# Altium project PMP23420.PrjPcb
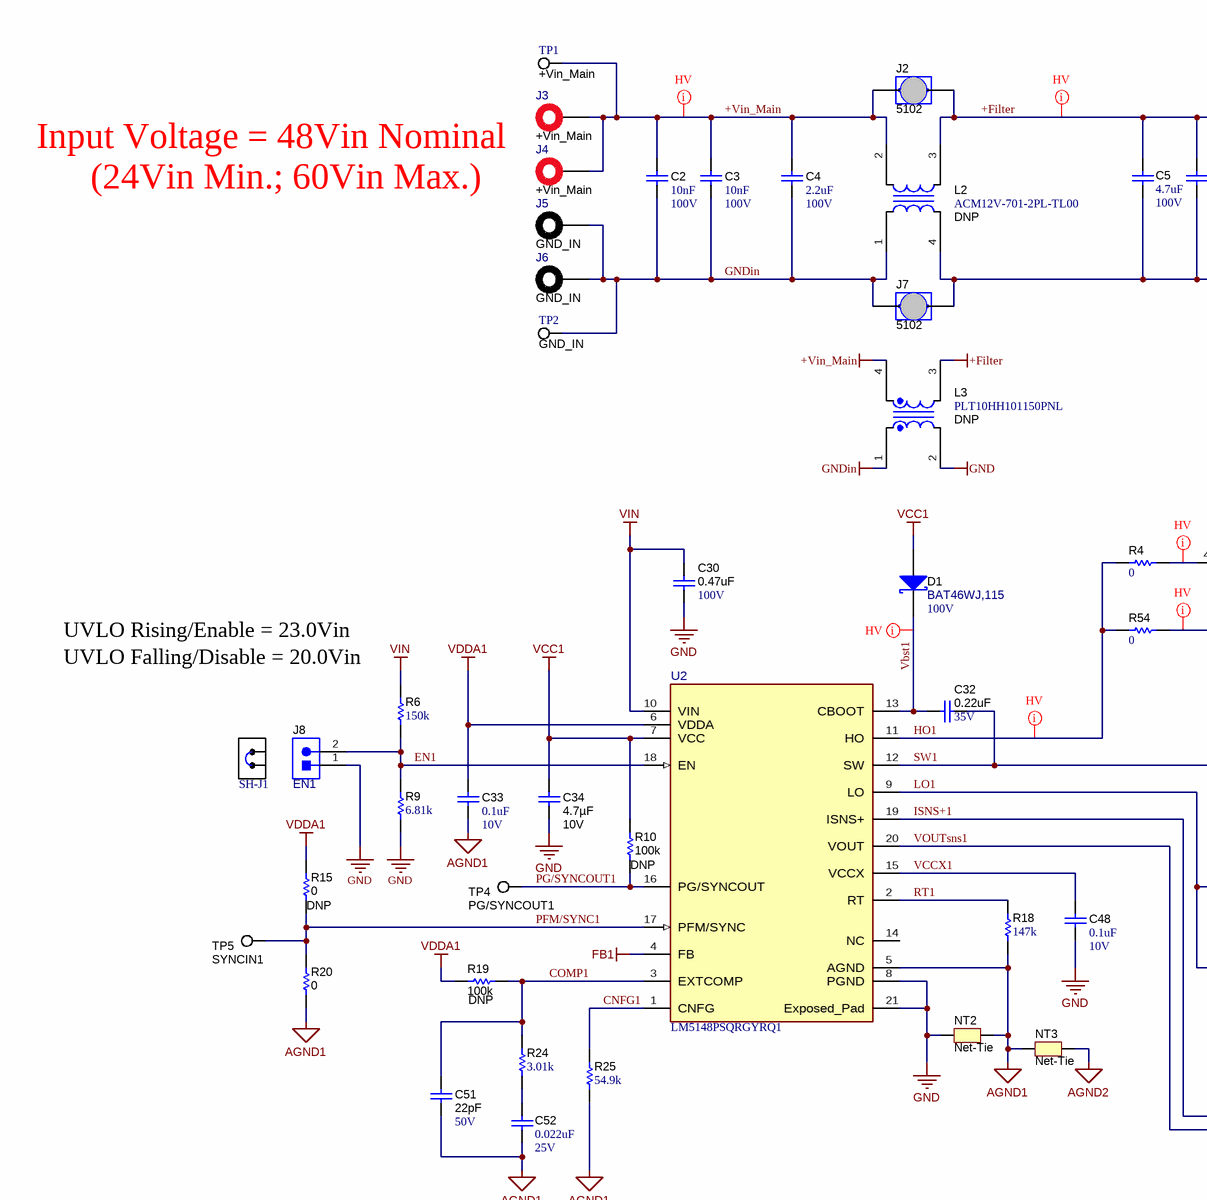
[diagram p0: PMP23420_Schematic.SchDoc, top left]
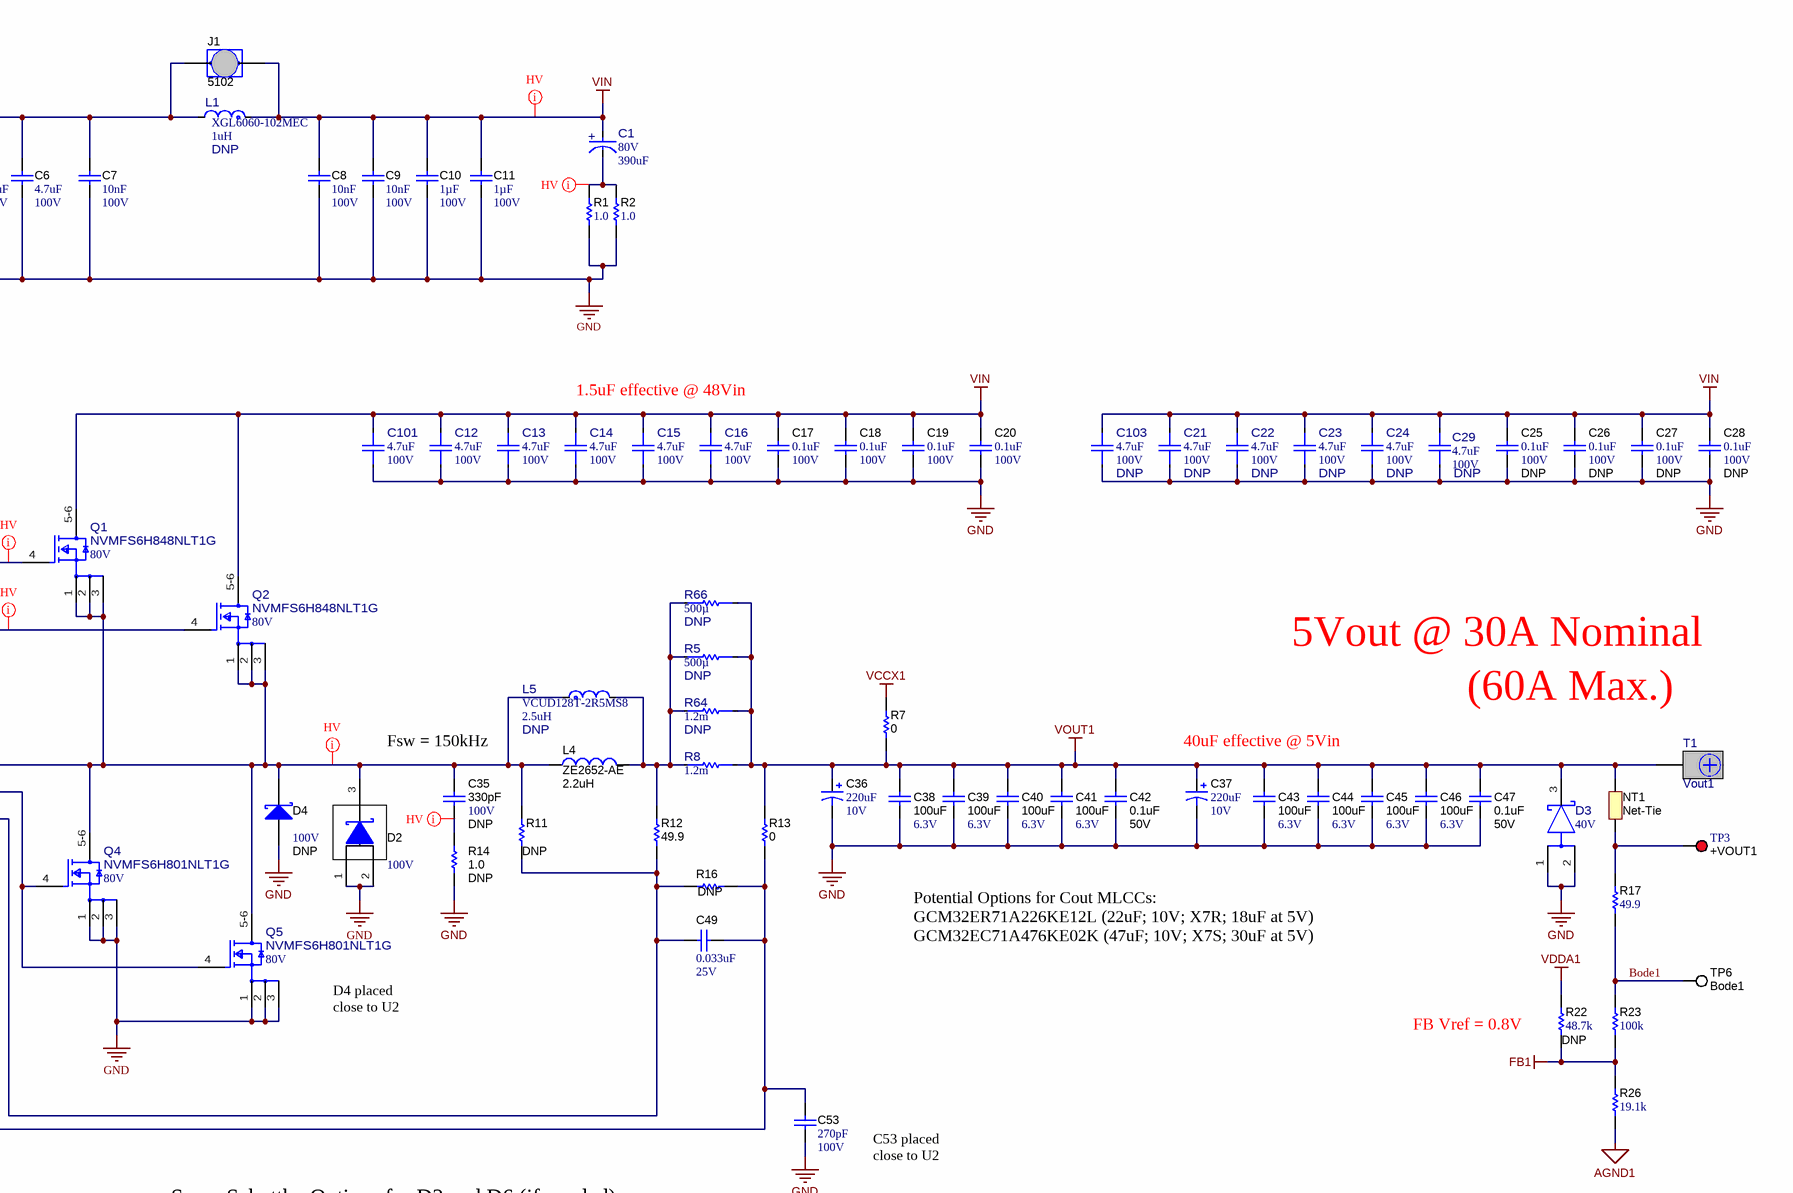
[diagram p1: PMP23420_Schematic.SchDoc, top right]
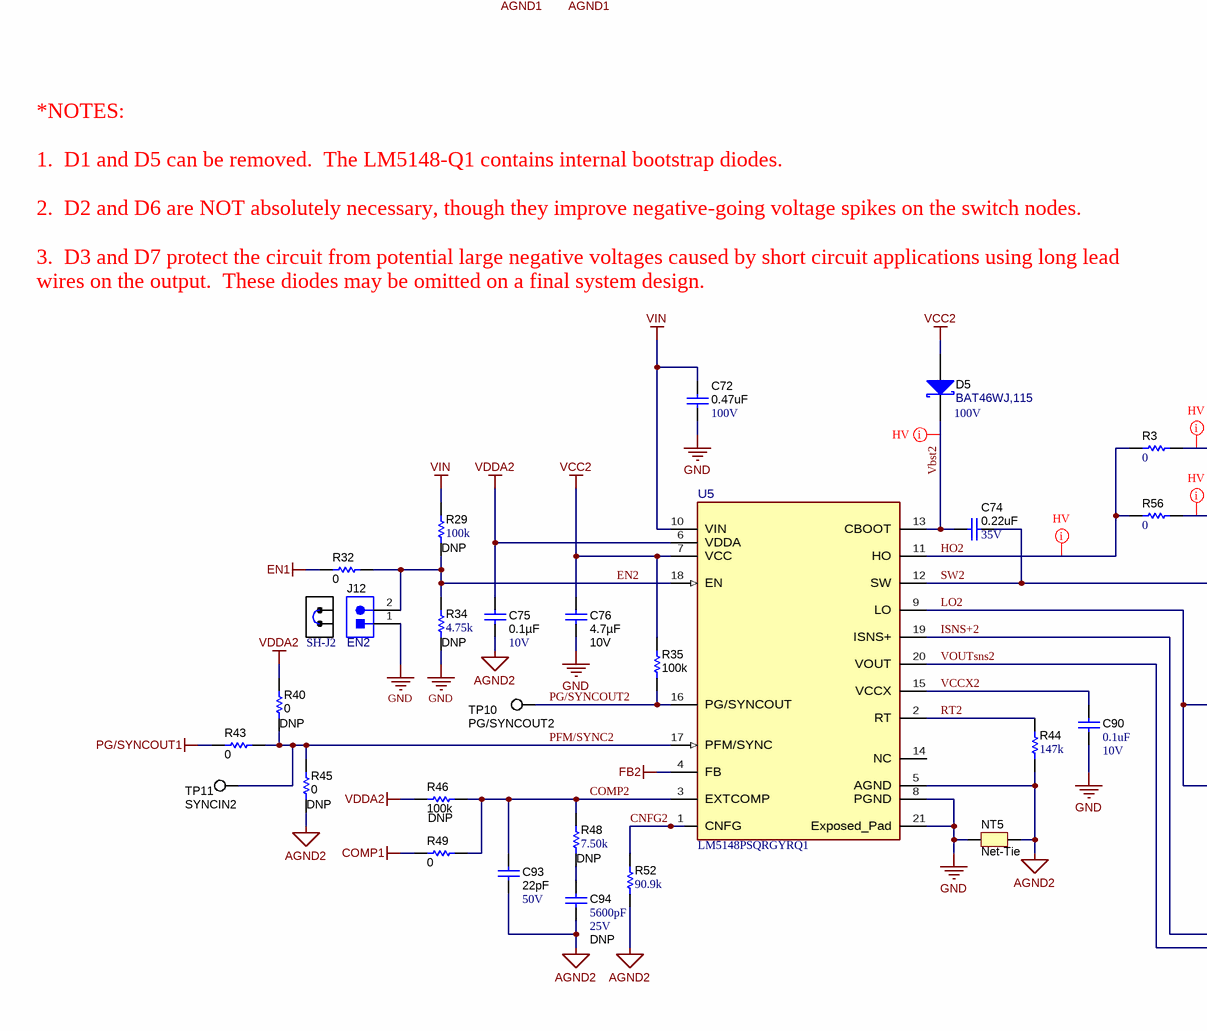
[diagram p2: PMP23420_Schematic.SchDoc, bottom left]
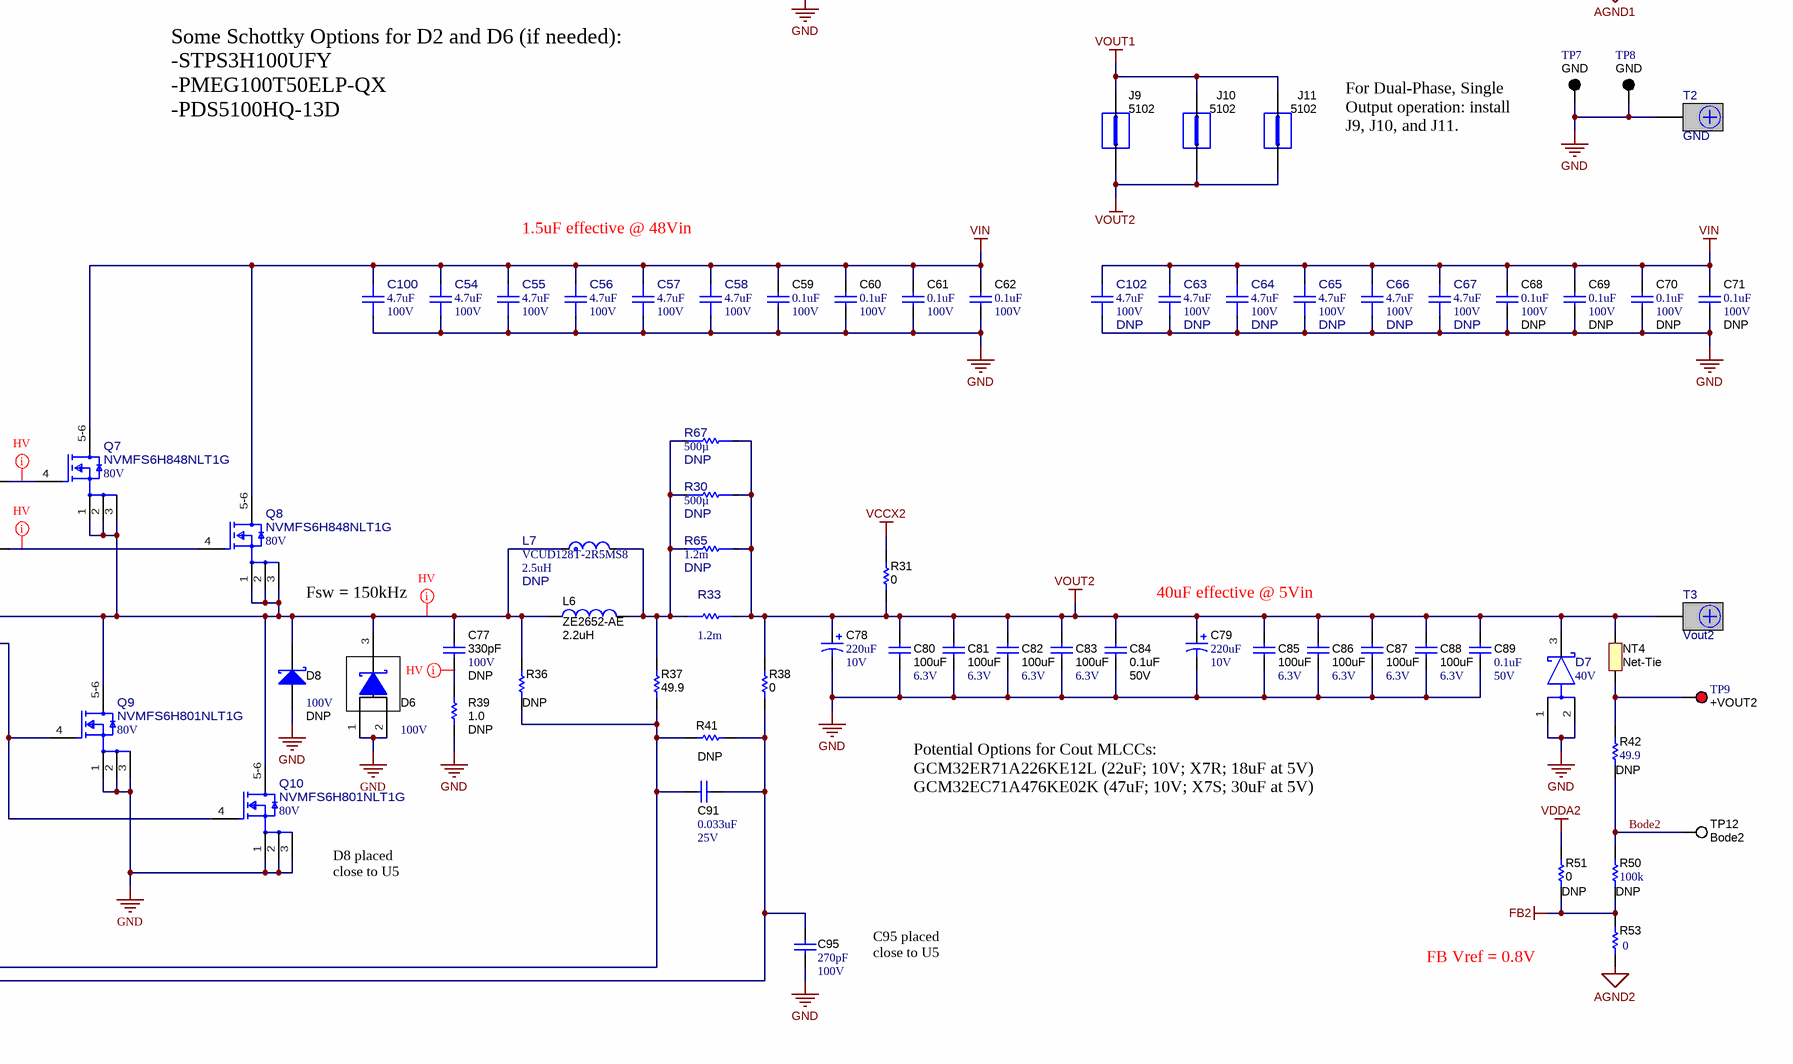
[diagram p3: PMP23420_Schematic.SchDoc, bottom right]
TID: PMP23420; TechSupport: http://www.ti.com/support; SCH_Rev: -1; PRJ_Title: LM5148-Q1 2-PH Buck Converter Using Si FETs; PRJ_Number: PMP23420; PRJ_Engineer: Hrag Kasparian; PCB_Rev: A; PCB_Layout: Hrag Kasparian; CopyrightYear: 2024
2 sheets, 228 parts. Net scope: global (net labels, ports and power ports of the same name join across sheets).
Board file: PMP23420.PcbDoc
Sheets:
  PMP23420_Schematic.SchDoc
  PMP23420_Hardware.SchDoc

## Sheet PMP23420_Schematic.SchDoc
size 558 x 431 mm; Date: Not shown in title block; ApprovedBy: Not shown in title block; CheckedBy: Not shown in title block; Author: Not shown in title block; CompanyName: Not shown in title block; Engineer: Not shown in title block; Organization: Not shown in title block; Address1: Not shown in title block; Address2: Not shown in title block; Address3: Not shown in title block; Address4: Not shown in title block; DocumentNumber: 1; Revision: Use project parameter SCH_Rev; SheetNumber: 1; SheetTotal: 2; PageSetup: Record=PageOptions¦CenterHorizontal=True¦CenterVertical=True¦PrintScale=1.00¦XCorrection=1.00¦YCorrection=1.00¦PrintKind=0¦BorderSize=5000000¦LeftOffset=0¦BottomOffset=0¦Orientation=2¦PaperLength=1000¦PaperWidth=1000¦Scale=100¦PaperSource=15¦PrintQuality=600¦MediaType=1¦DitherType=10¦PaperKind=Letter¦PrintScaleMode=1; SPICEModelCacheOPLTMGFQ: <root> / <DocumentId>OPLTMGFQ</DocumentId> / <CacheFrame Number="0"> / <Model Name="skydiode" Kind="MDL"> / <Text>*Default Schottky Diode / *Schottky Diode Pinout: A,K / .MODEL SKYDIODE D(EG=0.69 XTI=2)</Text> / </Model> / </CacheFrame> / </root>

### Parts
C1  VDC_V: 80V  ValueDisplayed: 390uF  [FP-EEE-TP1K391V_SMT_CAP_17MM0_17MM0-MFG]  (hidden comment: EEE-TP1K391V)
C2  Cap_F: 10nF  VDC_V: 100V  [0603_HV]  (hidden comment: GCM188R72A103KA37J)
C3  Cap_F: 10nF  VDC_V: 100V  [0603_HV]  (hidden comment: GCM188R72A103KA37J)
C4  VDC_V: 100V  ValueDisplayed: 2.2uF  [1206_180]  (hidden comment: CGA5L3X7S2A225K160AB)
C5  ValueDisplayed: 4.7uF  VDC_V: 100V  [1210_220]  (hidden comment: C3225X7S2A475K200AB)
C6  ValueDisplayed: 4.7uF  VDC_V: 100V  [1210_220]  (hidden comment: CGA6M3X7S2A475K200AB)
C7  Cap_F: 10nF  VDC_V: 100V  [0603L]  (hidden comment: GCM188R72A103KA37J)
C8  Cap_F: 10nF  VDC_V: 100V  [0603]  (hidden comment: GCM188R72A103KA37J)
C9  Cap_F: 10nF  VDC_V: 100V  [0603]  (hidden comment: GCM188R72A103KA37J)
C10  Cap_F: 1µF  VDC_V: 100V  [0805_150]  (hidden comment: 08051C105K4Z2A)
C11  Cap_F: 1µF  VDC_V: 100V  [0805_150]  (hidden comment: 08051C105K4Z2A)
C12  ValueDisplayed: 4.7uF  VDC_V: 100V  [FP-GCJ32DC72A475KE01L_1210-MFG]  (hidden comment: GCJ32DC72A475KE01L)
C13  ValueDisplayed: 4.7uF  VDC_V: 100V  [FP-GCJ32DC72A475KE01L_1210-MFG]  (hidden comment: GCJ32DC72A475KE01L)
C14  ValueDisplayed: 4.7uF  VDC_V: 100V  [FP-GCJ32DC72A475KE01L_1210-MFG]  (hidden comment: GCJ32DC72A475KE01L)
C15  ValueDisplayed: 4.7uF  VDC_V: 100V  [FP-GCJ32DC72A475KE01L_1210-MFG]  (hidden comment: GCJ32DC72A475KE01L)
C16  ValueDisplayed: 4.7uF  VDC_V: 100V  [FP-GCJ32DC72A475KE01L_1210-MFG]  (hidden comment: GCJ32DC72A475KE01L)
C17  VDC_V: 100V  ValueDisplayed: 0.1uF  [0603L]  (hidden comment: GCJ188R72A104KA01D)
C18  VDC_V: 100V  ValueDisplayed: 0.1uF  [0603L]  (hidden comment: GCJ188R72A104KA01D)
C19  VDC_V: 100V  ValueDisplayed: 0.1uF  [0603L]  (hidden comment: GCJ188R72A104KA01D)
C20  VDC_V: 100V  ValueDisplayed: 0.1uF  [0603L]  (hidden comment: GCJ188R72A104KA01D)
C21  DNP  ValueDisplayed: 4.7uF  VDC_V: 100V  [FP-GCJ32DC72A475KE01L_1210-MFG]
C22  DNP  ValueDisplayed: 4.7uF  VDC_V: 100V  [FP-GCJ32DC72A475KE01L_1210-MFG]
C23  DNP  ValueDisplayed: 4.7uF  VDC_V: 100V  [FP-GCJ32DC72A475KE01L_1210-MFG]
C24  DNP  ValueDisplayed: 4.7uF  VDC_V: 100V  [FP-GCJ32DC72A475KE01L_1210-MFG]
C25  DNP  VDC_V: 100V  ValueDisplayed: 0.1uF  [0603L]
C26  DNP  VDC_V: 100V  ValueDisplayed: 0.1uF  [0603L]
C27  DNP  VDC_V: 100V  ValueDisplayed: 0.1uF  [0603L]
C28  DNP  VDC_V: 100V  ValueDisplayed: 0.1uF  [0603L]
C29  DNP  ValueDisplayed: 4.7uF  VDC_V: 100V  [FP-GCJ32DC72A475KE01L_1210-MFG]
C30  value 0.47uF  Value1: 100V  [0805L]  (hidden comment: KAF21KR72A474KU)
C32  value 0.22uF  Value1: 35V  [0402L]  (hidden comment: CGA2B1X7R1V224K050BC)
C33  value 0.1uF  Value2: 10V  [0402L]  (hidden comment: C0402C104K8RACAUTO)
C34  Cap_F: 4.7µF  Value2: 10V  [0603L]  (hidden comment: GRM188Z71A475ME15D)
C35  DNP  value 330pF  Value1: 100V  [0603L]
C36  value 220uF  VDC_V: 10V  [7343-31]
C37  value 220uF  VDC_V: 10V  [7343-31]
C38  value 100uF  Value1: 6.3V  [1210L]  (hidden comment: GRT32EC70J107ME13K)
C39  value 100uF  Value1: 6.3V  [1210L]  (hidden comment: GRT32EC70J107ME13K)
C40  value 100uF  Value1: 6.3V  [1210L]  (hidden comment: GRT32EC70J107ME13K)
C41  value 100uF  Value1: 6.3V  [1210L]  (hidden comment: GRT32EC70J107ME13K)
C42  Value2: 50V  Cap_F: 0.1uF  [0603L]  (hidden comment: C0603C104K5RACTU)
C43  value 100uF  Value1: 6.3V  [1210L]  (hidden comment: GRT32EC70J107ME13K)
C44  value 100uF  Value1: 6.3V  [1210L]  (hidden comment: GRT32EC70J107ME13K)
C45  value 100uF  Value1: 6.3V  [1210L]  (hidden comment: GRT32EC70J107ME13K)
C46  value 100uF  Value1: 6.3V  [1210L]  (hidden comment: GRT32EC70J107ME13K)
C47  ValueDisplayed: 0.1uF  Value2: 50V  [0603L]  (hidden comment: Capacitor)
C48  value 0.1uF  Value2: 10V  [0402L]  (hidden comment: C0402C104K8RACAUTO)
C49  ValueDisplayed: 0.033uF  Value2: 25V  [0402L]  (hidden comment: CGA2B1X7R1E333K050BC)
C51  ValueDisplayed: 22pF  Value2: 50V  [0402L]  (hidden comment: CGA2B2NP01H220J050BA)
C52  ValueDisplayed: 0.022uF  VDC_V: 25V  [0402L]  (hidden comment: GCM155R71E223KA55D)
C53  ValueDisplayed: 270pF  VDC_V: 100V  [0402L]  (hidden comment: GRM155R72A271KA01D)
C54  ValueDisplayed: 4.7uF  VDC_V: 100V  [FP-GCJ32DC72A475KE01L_1210-MFG]  (hidden comment: GCJ32DC72A475KE01L)
C55  ValueDisplayed: 4.7uF  VDC_V: 100V  [FP-GCJ32DC72A475KE01L_1210-MFG]  (hidden comment: GCJ32DC72A475KE01L)
C56  ValueDisplayed: 4.7uF  VDC_V: 100V  [FP-GCJ32DC72A475KE01L_1210-MFG]  (hidden comment: GCJ32DC72A475KE01L)
C57  ValueDisplayed: 4.7uF  VDC_V: 100V  [FP-GCJ32DC72A475KE01L_1210-MFG]  (hidden comment: GCJ32DC72A475KE01L)
C58  ValueDisplayed: 4.7uF  VDC_V: 100V  [FP-GCJ32DC72A475KE01L_1210-MFG]  (hidden comment: GCJ32DC72A475KE01L)
C59  VDC_V: 100V  ValueDisplayed: 0.1uF  [0603L]  (hidden comment: GCJ188R72A104KA01D)
C60  VDC_V: 100V  ValueDisplayed: 0.1uF  [0603L]  (hidden comment: GCJ188R72A104KA01D)
C61  VDC_V: 100V  ValueDisplayed: 0.1uF  [0603L]  (hidden comment: GCJ188R72A104KA01D)
C62  VDC_V: 100V  ValueDisplayed: 0.1uF  [0603L]  (hidden comment: GCJ188R72A104KA01D)
C63  DNP  ValueDisplayed: 4.7uF  VDC_V: 100V  [FP-GCJ32DC72A475KE01L_1210-MFG]
C64  DNP  ValueDisplayed: 4.7uF  VDC_V: 100V  [FP-GCJ32DC72A475KE01L_1210-MFG]
C65  DNP  ValueDisplayed: 4.7uF  VDC_V: 100V  [FP-GCJ32DC72A475KE01L_1210-MFG]
C66  DNP  ValueDisplayed: 4.7uF  VDC_V: 100V  [FP-GCJ32DC72A475KE01L_1210-MFG]
C67  DNP  ValueDisplayed: 4.7uF  VDC_V: 100V  [FP-GCJ32DC72A475KE01L_1210-MFG]
C68  DNP  VDC_V: 100V  ValueDisplayed: 0.1uF  [0603L]
C69  DNP  VDC_V: 100V  ValueDisplayed: 0.1uF  [0603L]
C70  DNP  VDC_V: 100V  ValueDisplayed: 0.1uF  [0603L]
C71  DNP  VDC_V: 100V  ValueDisplayed: 0.1uF  [0603L]
C72  value 0.47uF  Value1: 100V  [0805L]  (hidden comment: KAF21KR72A474KU)
C74  value 0.22uF  Value1: 35V  [0402L]  (hidden comment: CGA2B1X7R1V224K050BC)
C75  ValueDisplayed: 0.1µF  Value2: 10V  [0402L]  (hidden comment: C0402C104K8RACAUTO)
C76  Cap_F: 4.7µF  Value2: 10V  [0603L]  (hidden comment: GRM188Z71A475ME15D)
C77  DNP  value 330pF  Value1: 100V  [0603L]
C78  value 220uF  VDC_V: 10V  [7343-31]
C79  value 220uF  VDC_V: 10V  [7343-31]
C80  value 100uF  Value1: 6.3V  [1210L]  (hidden comment: GRT32EC70J107ME13K)
C81  value 100uF  Value1: 6.3V  [1210L]  (hidden comment: GRT32EC70J107ME13K)
C82  value 100uF  Value1: 6.3V  [1210L]  (hidden comment: GRT32EC70J107ME13K)
C83  value 100uF  Value1: 6.3V  [1210L]  (hidden comment: GRT32EC70J107ME13K)
C84  value 0.1uF  Value2: 50V  [0603L]  (hidden comment: C0603C104K5RACTU)
C85  value 100uF  Value1: 6.3V  [1210L]  (hidden comment: GRT32EC70J107ME13K)
C86  value 100uF  Value1: 6.3V  [1210L]  (hidden comment: GRT32EC70J107ME13K)
C87  value 100uF  Value1: 6.3V  [1210L]  (hidden comment: GRT32EC70J107ME13K)
C88  value 100uF  Value1: 6.3V  [1210L]  (hidden comment: GRT32EC70J107ME13K)
C89  value 0.1uF  VDC_V: 50V  [0603L]  (hidden comment: C0603C104K5RACTU)
C90  value 0.1uF  Value2: 10V  [0402L]  (hidden comment: C0402C104K8RACAUTO)
C91  ValueDisplayed: 0.033uF  Value2: 25V  [0402L]  (hidden comment: CGA2B1X7R1E333K050BC)
C93  ValueDisplayed: 22pF  Value2: 50V  [0402L]  (hidden comment: CGA2B2NP01H220J050BA)
C94  DNP  ValueDisplayed: 5600pF  VDC_V: 25V  [0402L]
C95  ValueDisplayed: 270pF  VDC_V: 100V  [0402L]  (hidden comment: GRM155R72A271KA01D)
C100  ValueDisplayed: 4.7uF  VDC_V: 100V  [FP-GCJ32DC72A475KE01L_1210-MFG]  (hidden comment: GCJ32DC72A475KE01L)
C101  ValueDisplayed: 4.7uF  VDC_V: 100V  [FP-GCJ32DC72A475KE01L_1210-MFG]  (hidden comment: GCJ32DC72A475KE01L)
C102  DNP  ValueDisplayed: 4.7uF  VDC_V: 100V  [FP-GCJ32DC72A475KE01L_1210-MFG]
C103  DNP  ValueDisplayed: 4.7uF  VDC_V: 100V  [FP-GCJ32DC72A475KE01L_1210-MFG]
D1  BAT46WJ,115  value 100V  [SOD-323F]
D2  value 100V  [POWERDI5]  (hidden comment: PDS5100HQ-13)
D3  value 40V  [FP-SS10P4HM3_A/H_SMPC-MFG]  (hidden comment: SS10P4HM3_A/H)
D4  DNP  value 100V  [SOD-123]
D5  BAT46WJ,115  value 100V  [SOD-323F]
D6  value 100V  [POWERDI5]  (hidden comment: PDS5100HQ-13)
D7  value 40V  [FP-SS10P4HM3_A/H_SMPC-MFG]  (hidden comment: SS10P4HM3_A/H)
D8  DNP  value 100V  [SOD-123]
J1  PartNumber: 5102  [Keystone_5102]
J2  PartNumber: 5102  [Keystone_5102]
J3  +Vin_Main  [Cinch_108-0902-001]
J4  +Vin_Main  [Cinch_108-0902-001]
J5  GND_IN  [Cinch_108-0903-001]
J6  GND_IN  [Cinch_108-0903-001]
J7  PartNumber: 5102  [Keystone_5102]
J8  EN1  [TSW-102-07-G-S]
J9  PartNumber: 5102  [Keystone_5102]
J10  PartNumber: 5102  [Keystone_5102]
J11  PartNumber: 5102  [Keystone_5102]
J12  EN2  [TSW-102-07-G-S]
L1  DNP  value 1uH  Part Number: XGL6060-102MEC  [FP-XGL6060-102MEC_SMT2_6MM51_6MM71-MFG]
L2  DNP  PartNumber: ACM12V-701-2PL-TL00  [TDK_ACM12V]
L3  DNP  PartNumber: PLT10HH101150PNL  [MuRata_PLT10H]
L4  value 2.2uH  (hidden comment: ZE2652-AE)
L5  DNP  value 2.5uH  Part Number: VCUD128T-2R5MS8  [FP-VCUD128T-2R5MS8_SMT_IND_13MM3_12MM8-MFG]
L6  value 2.2uH  (hidden comment: ZE2652-AE)
L7  DNP  value 2.5uH  PartNumber: VCUD128T-2R5MS8  [FP-VCUD128T-2R5MS8_SMT_IND_13MM3_12MM8-MFG]
NT1  Net-Tie  [Net-Tie_10mil]  (net tie, no BOM)
NT2  Net-Tie  [Net-Tie_10mil]  (net tie, no BOM)
NT3  Net-Tie  [Net-Tie_10mil]  (net tie, no BOM)
NT4  Net-Tie  [Net-Tie_10mil]  (net tie, no BOM)
NT5  Net-Tie  [Net-Tie_10mil]  (net tie, no BOM)
Q1  NVMFS6H848NLT1G  Drain To Source Breakdown Voltage: 80V  [FP-NVMFS6H848NLT1G_DFN5-5x6-MFG]
Q2  NVMFS6H848NLT1G  Drain To Source Breakdown Voltage: 80V  [FP-NVMFS6H848NLT1G_DFN5-5x6-MFG]
Q4  NVMFS6H801NLT1G  Drain To Source Breakdown Voltage: 80V  [FP-NVMFS6H801NLT1G_DFN5-MFG]
Q5  NVMFS6H801NLT1G  Drain To Source Breakdown Voltage: 80V  [FP-NVMFS6H801NLT1G_DFN5-MFG]
Q7  NVMFS6H848NLT1G  Drain To Source Breakdown Voltage: 80V  [FP-NVMFS6H848NLT1G_DFN5-5x6-MFG]
Q8  NVMFS6H848NLT1G  Drain To Source Breakdown Voltage: 80V  [FP-NVMFS6H848NLT1G_DFN5-5x6-MFG]
Q9  NVMFS6H801NLT1G  Drain To Source Breakdown Voltage: 80V  [FP-NVMFS6H801NLT1G_DFN5-MFG]
Q10  NVMFS6H801NLT1G  Drain To Source Breakdown Voltage: 80V  [FP-NVMFS6H801NLT1G_DFN5-MFG]
R1  ValueDisplayed: 1.0  [2512]  (hidden comment: CRCW25121R00JNEG)
R2  ValueDisplayed: 1.0  [2512]  (hidden comment: CRCW25121R00JNEG)
R3  ValueDisplayed: 0  [0603L]  (hidden comment: RMCF0603ZT0R00)
R4  ValueDisplayed: 0  [0603L]  (hidden comment: RMCF0603ZT0R00)
R5  DNP  value 500µ  [FP-PML100HZPJV0L5_1225-MFG]
R6  ValueDisplayed: 150k  [0603L]  (hidden comment: CRCW0603150KFKEA)
R7  ValueDisplayed: 0  [0402L]  (hidden comment: CRCW04020000Z0EDHP)
R8  Res_ohm: 1.2m  [FP-Y14830R00120F9R_2512-MFG]  (hidden comment: Y14830R00120F9R)
R9  ValueDisplayed: 6.81k  [0402L]  (hidden comment: CRCW04026K81FKED)
R10  DNP  ValueDisplayed: 100k  [0402L]
R11  DNP  [0603L]
R12  ValueDisplayed: 49.9  [0402L]  (hidden comment: CRCW040249R9FKED)
R13  Value1: 0  [FP-RMCF0402ZT0R00_0402 (1005 metric)-0]  (hidden comment: RMCF0402ZT0R00)
R14  DNP  value 1.0  [1210L]
R15  DNP  ValueDisplayed: 0  [0402L]
R16  DNP  [0402L]
R17  ValueDisplayed: 49.9  [0603L]  (hidden comment: CRCW060349R9FKEA)
R18  ValueDisplayed: 147k  [0402L]  (hidden comment: CRCW0402147KFKED)
R19  DNP  ValueDisplayed: 100k  [0402L]
R20  ValueDisplayed: 0  [0402L]
R22  DNP  ValueDisplayed: 48.7k  [0402L]
R23  ValueDisplayed: 100k  [0402L]  (hidden comment: RMCF0402FT100K)
R24  ValueDisplayed: 3.01k  [0402L]  (hidden comment: CRCW04023K01FKED)
R25  ValueDisplayed: 54.9k  [0402L]  (hidden comment: CRCW040254K9FKED)
R26  ValueDisplayed: 19.1k  [0402L]  (hidden comment: CRCW040219K1FKED)
R29  DNP  ValueDisplayed: 100k  [0603L]
R30  DNP  value 500µ  [FP-PML100HZPJV0L5_1225-MFG]
R31  ValueDisplayed: 0  [0402L]  (hidden comment: CRCW04020000Z0EDHP)
R32  ValueDisplayed: 0  [0402L]  (hidden comment: CRCW04020000Z0EDHP)
R33  Res_ohm: 1.2m  [FP-Y14830R00120F9R_2512-MFG]  (hidden comment: Y14830R00120F9R)
R34  DNP  ValueDisplayed: 4.75k  [0402L]
R35  ValueDisplayed: 100k  [0402L]  (hidden comment: RMCF0402FT100K)
R36  DNP  [0603L]
R37  ValueDisplayed: 49.9  [0402L]  (hidden comment: CRCW040249R9FKED)
R38  Value1: 0  [FP-RMCF0402ZT0R00_0402 (1005 metric)-0]  (hidden comment: RMCF0402ZT0R00)
R39  DNP  value 1.0  [1210L]
R40  DNP  ValueDisplayed: 0  [0402L]
R41  DNP  [0402L]
R42  DNP  ValueDisplayed: 49.9  [0603L]
R43  ValueDisplayed: 0  [0402L]  (hidden comment: CRCW04020000Z0EDHP)
R44  ValueDisplayed: 147k  [0402L]  (hidden comment: CRCW0402147KFKED)
R45  DNP  ValueDisplayed: 0  [0402L]
R46  DNP  ValueDisplayed: 100k  [0402L]
R48  DNP  ValueDisplayed: 7.50k  [0402L]
R49  ValueDisplayed: 0  [0402L]  (hidden comment: CRCW04020000Z0EDHP)
R50  DNP  ValueDisplayed: 100k  [0402L]
R51  DNP  Value1: 0  [FP-RMCF0402ZT0R00_0402 (1005 metric)-0]
R52  ValueDisplayed: 90.9k  [0402L]  (hidden comment: CRCW040290K9FKED)
R53  value 0  [FP-RMCF0402ZT0R00_0402 (1005 metric)-0]  (hidden comment: RMCF0402ZT0R00)
R54  ValueDisplayed: 0  [0603L]  (hidden comment: RMCF0603ZT0R00)
R56  ValueDisplayed: 0  [0603L]  (hidden comment: RMCF0603ZT0R00)
R64  DNP  Res_ohm: 1.2m  [FP-Y14830R00120F9R_2512-MFG]
R65  DNP  Res_ohm: 1.2m  [FP-Y14830R00120F9R_2512-MFG]
R66  DNP  value 500µ  [FP-PML100HZPJV0L5_1225-MFG]
R67  DNP  value 500µ  [FP-PML100HZPJV0L5_1225-MFG]
SH-J1  60900213421  [Wurth_60900213421]  (value not drawn)
SH-J2  60900213421  [Wurth_60900213421]  (value not drawn)
T1  Vout1  [CB70-14-CY]
T2  GND  [CB70-14-CY]
T3  Vout2  [CB70-14-CY]
TP1  +Vin_Main  [Testpoint_Keystone_Compact]
TP2  GND_IN  [Testpoint_Keystone_Compact]
TP3  +VOUT1  [Keystone5010]
TP4  PG/SYNCOUT1  [Keystone5012]
TP5  SYNCIN1  [Keystone5012]
TP6  Bode1  [Keystone5012]
TP7  GND  [Keystone5011]
TP8  GND  [Keystone5011]
TP9  +VOUT2  [Keystone5010]
TP10  PG/SYNCOUT2  [Keystone5012]
TP11  SYNCIN2  [Keystone5012]
TP12  Bode2  [Keystone5012]
U2  LM5148PSQRGYRQ1  [RGY0020B-MFG]
U5  LM5148PSQRGYRQ1  [RGY0020B-MFG]

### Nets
+Filter: C5.2 C6.2 C7.1 J1.2 J2.1 L1.2 L2.3 L3.3
+Vin_Main: C2.1 C3.1 C4.1 J2.2 J3.1 J4.1 L2.2 L3.4 TP1.1
AGND1: C33.1 C51.2 C52.2 NT2.2 NT3.1 R18.2 R20.2 R25.1 R26.1 U2.5(AGND)
AGND2: C75.1 C93.2 C94.2 NT3.2 NT5.2 R44.2 R45.2 R52.1 R53.1 U5.5(AGND)
COMP1: C51.1 R19.1 R24.2 R49.2 U2.3(EXTCOMP)
EN1: J8.2 R6.1 R9.2 R32.2 U2.18(EN)
FB1: R22.2 R23.1 R26.2 U2.4(FB)
FB2: R50.1 R51.2 R53.2 U5.4(FB)
GND: C5.1 C6.1 C7.2 C8.2 C9.2 C10.2 C11.2 C12.1 C13.1 C14.1 C15.1 C16.1 C17.2 C18.2 C19.2 C20.2 C21.1 C22.1 C23.1 C24.1 C25.2 C26.2 C27.2 C28.2 C29.1 C30.2 C34.2 C36.2(-) C37.2(-) C38.2 C39.2 C40.2 C41.2 C42.2 C43.2 C44.2 C45.2 C46.2 C47.2 C48.1 C53.1 C54.1 C55.1 C56.1 C57.1 C58.1 C59.2 C60.2 C61.2 C62.2 C63.1 C64.1 C65.1 C66.1 C67.1 C68.2 C69.2 C70.2 C71.2 C72.2 C76.2 C78.2(-) C79.2(-) C80.2 C81.2 C82.2 C83.2 C84.2 C85.2 C86.2 C87.2 C88.2 C89.2 C90.1 C95.1 C100.1 C101.1 C102.1 C103.1 D2.1(A) D2.2(A) D3.1(Anode) D3.2(Anode) D4.2(A) D6.1(A) D6.2(A) D7.1(Anode) D7.2(Anode) D8.2(A) J7.1 J8.1 J12.1 L2.4 L3.2 NT2.1 NT5.1 Q4.1(S) Q4.2(S) Q4.3(S) Q5.1(S) Q5.2(S) Q5.3(S) Q9.1(S) Q9.2(S) Q9.3(S) Q10.1(S) Q10.2(S) Q10.3(S) R1.1 R2.1 R9.1 R14.1 R34.1 R39.1 T2.1 TP7.1 TP8.1 U2.8(PGND) U2.21(Exposed_Pad) U5.8(PGND) U5.21(Exposed_Pad)
GNDin: C2.2 C3.2 C4.2 J5.1 J6.1 J7.2 L2.1 L3.1 TP2.1
PG/SYNCOUT1: R10.1 R43.2 TP4.1 U2.16(PG/SYNCOUT)
VCC1: C34.1 D1.2(A) R10.2 U2.7(VCC)
VCC2: C76.1 D5.2(A) R35.2 U5.7(VCC)
VCCX1: C48.2 R7.2 U2.15(VCCX)
VCCX2: C90.2 R31.1 U5.15(VCCX)
VDDA1: C33.2 R15.1 R19.2 R22.1 U2.6(VDDA)
VDDA2: C75.2 R40.1 R46.1 R51.1 U5.6(VDDA)
VIN: C1.2(ANODE) C8.1 C9.1 C10.1 C11.1 C12.2 C13.2 C14.2 C15.2 C16.2 C17.1 C18.1 C19.1 C20.1 C21.2 C22.2 C23.2 C24.2 C25.1 C26.1 C27.1 C28.1 C29.2 C30.1 C54.2 C55.2 C56.2 C57.2 C58.2 C59.1 C60.1 C61.1 C62.1 C63.2 C64.2 C65.2 C66.2 C67.2 C68.1 C69.1 C70.1 C71.1 C72.1 C100.2 C101.2 C102.2 C103.2 J1.1 L1.1 Q1.5-6(D) Q2.5-6(D) Q7.5-6(D) Q8.5-6(D) R6.2 R29.2 U2.10(VIN) U5.10(VIN)
VOUT1: C36.1(+) C37.1(+) C38.1 C39.1 C40.1 C41.1 C42.1 C43.1 C44.1 C45.1 C46.1 C47.1 D3.3(Cathode) J9.2 J10.2 J11.2 NT1.2 R5.2 R7.1 R8.2 R13.2 R64.2 R66.2 T1.1
VOUT2: C78.1(+) C79.1(+) C80.1 C81.1 C82.1 C83.1 C84.1 C85.1 C86.1 C87.1 C88.1 C89.1 D7.3(Cathode) J9.1 J10.1 J11.1 NT4.2 R30.2 R31.2 R33.2 R38.2 R65.2 R67.2 T3.1
Bode1: R17.1 R23.2 TP6.1
Bode2: R42.1 R50.2 TP12.1
CNFG1: R25.2 U2.1(CNFG)
CNFG2: R52.2 U5.1(CNFG)
COMP2: C93.1 R46.2 R48.2 R49.1 U5.3(EXTCOMP)
EN2: J12.2 R29.1 R32.1 R34.2 U5.18(EN)
HO1: R4.1 R54.1 U2.11(HO)
HO2: R3.1 R56.1 U5.11(HO)
ISNS+1: C49.2 R11.1 R12.1 R16.2 U2.19(ISNS+)
ISNS+2: C91.2 R36.1 R37.1 R41.2 U5.19(ISNS+)
LO1: Q4.4(G) Q5.4(G) U2.9(LO)
LO2: Q9.4(G) Q10.4(G) U5.9(LO)
PFM/SYNC1: R15.2 R20.1 TP5.1 U2.17(PFM/SYNC)
PFM/SYNC2: R40.2 R43.1 R45.1 TP11.1 U5.17(PFM/SYNC)
PG/SYNCOUT2: R35.1 TP10.1 U5.16(PG/SYNCOUT)
RT1: R18.1 U2.2(RT)
RT2: R44.1 U5.2(RT)
SW1: C32.2 C35.1 D2.3(K) D4.1(K) L4.1 L5.1 Q1.1(S) Q1.2(S) Q1.3(S) Q2.1(S) Q2.2(S) Q2.3(S) Q4.5-6(D) Q5.5-6(D) R11.2 U2.12(SW)
SW2: C74.2 C77.1 D6.3(K) D8.1(K) L6.1 L7.1 Q7.1(S) Q7.2(S) Q7.3(S) Q8.1(S) Q8.2(S) Q8.3(S) Q9.5-6(D) Q10.5-6(D) R36.2 U5.12(SW)
Vbst1: C32.1 D1.1(K) U2.13(CBOOT)
Vbst2: C74.1 D5.1(K) U5.13(CBOOT)
VOUTsns1: C49.1 C53.2 R13.1 R16.1 U2.20(VOUT)
VOUTsns2: C91.1 C95.2 R38.1 R41.1 U5.20(VOUT)
NetC1_1: C1.1(CATHODE) R1.2 R2.2
NetC35_2: C35.2 R14.2
NetC52_1: C52.1 R24.1
NetC77_2: C77.2 R39.2
NetC94_1: C94.1 R48.1
NetL4_2: L4.2 L5.2 R5.1 R8.1 R12.2 R64.1 R66.1
NetL6_2: L6.2 L7.2 R30.1 R33.1 R37.2 R65.1 R67.1
NetNT1_1: NT1.1 R17.2 TP3.1
NetNT4_1: NT4.1 R42.2 TP9.1
NetQ1_4: Q1.4(G) R4.2
NetQ2_4: Q2.4(G) R54.2
NetQ7_4: Q7.4(G) R3.2
NetQ8_4: Q8.4(G) R56.2

Not connected (* = marked no-connect by the designer): U2 14(NC); U5 14(NC)

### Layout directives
net class HV: +Filter, +Vin_Main, HO1, HO2, NetC1_1, NetC35_2, NetC77_2, NetQ1_4, NetQ2_4, NetQ7_4, NetQ8_4, SW1, SW2, Vbst1, Vbst2, VIN

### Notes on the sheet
- (near J3) Input Voltage = 48Vin Nominal
- (24Vin Min.; 60Vin Max.)
- 1.5uF effective @ 48Vin
- UVLO Rising/Enable = 23.0Vin
- (near R6) UVLO Falling/Disable = 20.0Vin
- 5Vout @ 30A Nominal
- (60A Max.)
- Fsw = 150kHz
- 40uF effective @ 5Vin
- Potential Options for Cout MLCCs:
  GCM32ER71A226KE12L (22uF; 10V; X7R; 18uF at 5V)
  GCM32EC71A476KE02K (47uF; 10V; X7S; 30uF at 5V)
- D4 placed close to U2
- (near R22) FB Vref = 0.8V
- C53 placed close to U2
- Some Schottky Options for D2 and D6 (if needed):
  -STPS3H100UFY
  -PMEG100T50ELP-QX
  -PDS5100HQ-13D
- For Dual-Phase, Single Output operation: install J9, J10, and J11.
- *NOTES:
  1.  D1 and D5 can be removed.  The LM5148-Q1 contains internal bootstrap diodes.
  2.  D2 and D6 are NOT absolutely necessary, though they improve negative-going voltage spikes on the switch nodes.
  3.  D3 and D7 protect the circuit from potential large negative voltages caused by short circuit applications using long lead wires on the output.  These diodes may be omitted on a final system design.
- (near Q10) D8 placed close to U5
- C95 placed close to U5
- FB Vref = 0.8V

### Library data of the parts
C1 = CMP-0048820-1: Cap Aluminum Lytic 390uF 80V 20% (16 X 16.5mm) SMD 0.1 Ohm 1900mA 3000h 125°C Automotive T/R; Manufacturer: Panasonic; Value: 390µF; SizeZ_mm: 17.1mm; AEC Qualified: No; IRMS_A: 1.9A; Dissipation Factor: 12%; Esr: 0.1; Leakage Current: 312uA; Life: 3000Hours
C2 = CMP-0084773-1: CAP, CERM, 0.01 µF, 100 V,+/- 10%, X7R, AEC-Q200 Grade 1, 0603; Manufacturer: MuRata; Polarized: N; Value: 0.01uF; ValueDisplayed: 0.01µF; U/M: EA; TaMin_C: -55°C; TaMax_C: 125°C; Cap_Case: 0603; AEC Category: Q200; AEC Grade: 1; AEC Qualified: Y; SizeArea_mm2: 1.28; SizeAreaWB_mm2: 4.68; SizeX_mm: 1.6; SizeY_mm: 0.8
C3 C7 = CMP-0084773-1: CAP, CERM, 0.01 µF, 100 V,+/- 10%, X7R, AEC-Q200 Grade 1, 0603; Manufacturer: MuRata; TaMin_C: -55°C; Polarized: N; SizeAreaWB_mm2: 4.68; U/M: EA; Value: 0.01uF; TaMax_C: 125°C; SizeZ_mm: 1; SizeX_mm: 1.6; SizeY_mm: 0.8; Cap_Case: 0603; SizeArea_mm2: 1.28; AEC Qualified: Y; AEC Category: Q200; ValueDisplayed: 0.01µF
C4 = CMP-0008790-2: CAP, CERM, 2.2 uF, 100 V, +/- 10%, X7S, AEC-Q200 Grade 1, 1206; Manufacturer: TDK; TaMin_C: -55°C; ESR_ohm: 5.718m; Polarized: N; SizeAreaWB_mm2: 10.92; Value1: 0.005718 ohm; U/M: EA; Value: 2.2uF; TaMax_C: 125°C; SizeZ_mm: 1.8; SizeX_mm: 3.2; SizeY_mm: 1.6; SizeArea_mm2: 5.12; AEC Qualified: Y; Cap_F: 2.2µF; IRMS_A: 3.03632A; AEC Grade: 1; AEC Category: Q200
C5 = CMP-0009134-2: CAP, CERM, 4.7 uF, 100 V, +/- 10%, X7S, 1210; Manufacturer: TDK; AEC Qualified: N; SizeZ_mm: 2.2; Cap_F: 4.7µF; TaMin_C: -55°C; ESR_ohm: 4.236m; SizeAreaWB_mm2: 14.7; Value1: 0.004236 ohm; U/M: EA; Value: 4.7uF; TaMax_C: 125°C; SizeX_mm: 3.2; SizeY_mm: 2.5; SizeArea_mm2: 8; IRMS_A: 3.57337A; AEC Category: Q200
C6 = CMP-0009150-2: CAP, CERM, 4.7 uF, 100 V, +/- 10%, X7S, AEC-Q200 Grade 1, 1210; Manufacturer: TDK; AEC Qualified: Y; SizeZ_mm: 2.2; Cap_F: 4.7µF; AEC Grade: 1; TaMin_C: -55°C; ESR_ohm: 4.236m; Polarized: N; SizeAreaWB_mm2: 14.7; Value1: 0.004236 ohm; U/M: EA; Value: 4.7uF; TaMax_C: 125°C; SizeX_mm: 3.2; SizeY_mm: 2.5; SizeArea_mm2: 8; IRMS_A: 3.57337A; AEC Category: Q200
C8 C9 = CMP-0084773-1: CAP, CERM, 0.01 µF, 100 V,+/- 10%, X7R, AEC-Q200 Grade 1, 0603; Manufacturer: MuRata; TaMin_C: -55°C; Polarized: N; SizeAreaWB_mm2: 4.68; U/M: EA; Value: 0.01uF; TaMax_C: 125°C; SizeZ_mm: 1; SizeX_mm: 1.6; SizeY_mm: 0.8; SizeArea_mm2: 1.28; AEC Qualified: Y; AEC Category: Q200; ValueDisplayed: 0.01µF
C10 C11 = CMP-0861070-1: CAP, CERM, 1 µF, 100 V,+/- 10%, X7R, AEC-Q200 Grade 1, 0805; Manufacturer: AVX; Polarized: N; Value: 1uF; U/M: EA; TaMin_C: -55°C; TaMax_C: 125°C; Cap_Case: 0805; AEC Category: Q200; AEC Grade: 1; AEC Qualified: Y; SizeArea_mm2: 2.5; SizeAreaWB_mm2: 6.75; SizeX_mm: 2; SizeY_mm: 1.25; SizeZ_mm: 1.5
C12-C16 C55-C58 C101 = CMP-0093675-1: 4.7uF ±10% 100V Ceramic Capacitor X7S 1210 (3225 Metric); Manufacturer: Murata; AEC Qualified: Yes; TempCo: 22%; SizeZ_mm: 2.3mm; Cap_F: 4.7µF; AEC Grade: Grade 1; Value: 4.7µF
C17-C20 C59-C62 = CMP-0064935-4: CAP, CERM, 0.1 uF, 100 V,+/- 10%, X7R, AEC-Q200 Grade 1, 0603; Manufacturer: MuRata; TaMin_C: -55°C; Polarized: N; SizeAreaWB_mm2: 4.68; Value1: Unknown; U/M: EA; Value: 0.1uF; TaMax_C: 125°C; SizeZ_mm: 1; SizeX_mm: 1.6; SizeY_mm: 0.8; Cap_Case: 0603; SizeArea_mm2: 1.28; AEC Qualified: Y; Cap_F: 100nF; AEC Category: Q200
C21-C24 C29 C63-C67 C103 = CMP-0093675-1: 4.7uF ±10% 100V Ceramic Capacitor X7S 1210 (3225 Metric); Manufacturer: Murata; PartNumber: GCJ32DC72A475KE01L; AEC Qualified: Yes; TempCo: 22%; SizeZ_mm: 2.3mm; Cap_F: 4.7µF; AEC Grade: Grade 1; Value: 4.7µF
C25-C28 C68-C71 = CMP-0064935-4: CAP, CERM, 0.1 uF, 100 V,+/- 10%, X7R, AEC-Q200 Grade 1, 0603; Manufacturer: MuRata; PartNumber: GCJ188R72A104KA01D; TaMin_C: -55°C; Polarized: N; SizeAreaWB_mm2: 4.68; Value1: Unknown; U/M: EA; Value: 0.1uF; TaMax_C: 125°C; SizeZ_mm: 1; SizeX_mm: 1.6; SizeY_mm: 0.8; Cap_Case: 0603; SizeArea_mm2: 1.28; AEC Qualified: Y; Cap_F: 100nF; AEC Category: Q200
C30 C72 = Capacitor: CAP, CERM, xxxF, xxV, [TempCo], xx%, [PackageReference]; Manufacturer: Kyocera AVX; Polarized: N; U/M: EA
C32 C74 = Capacitor: CAP, CERM, 0.22uF, 35V, X7R, 10%, 0402; Manufacturer: TDK; Polarized: N; U/M: EA
C33 C48 C90 = CMP-0079150-1: CAP, CERM, 0.1 µF, 10 V,+/- 10%, X7R, AEC-Q200 Grade 1, 0402; Manufacturer: Kemet; Polarized: N; ValueDisplayed: 0.1µF; U/M: EA; Cap_F: 100nF; TaMin_C: -55°C; TaMax_C: 125°C; Cap_Case: 0402; AEC Category: Q200; AEC Grade: 1; AEC Qualified: Y; SizeArea_mm2: 0.5; SizeAreaWB_mm2: 3; SizeZ_mm: 0.6
C34 C76 = CMP-0007498-4: CAP, CERM, 4.7 uF, 10 V, +/- 20%, X7R, 0603; Manufacturer: MuRata; Polarized: N; Value: 4.7uF; U/M: EA; Value1: Unknown; TaMin_C: -55°C; TaMax_C: 125°C; Cap_Case: 0603; AEC Category: Q200; SizeArea_mm2: 1.28; SizeAreaWB_mm2: 4.68; SizeX_mm: 1.6; SizeY_mm: 0.8; SizeZ_mm: 1
C35 C77 = Capacitor: CAP, CERM, 330F, 100V, C0G, 5%, 0603; Manufacturer: Murata; PartNumber: GCM1885C2A331JA16D; Polarized: N; U/M: EA
C36 C37 C78 C79 = CMP-0012661-3: CAP, Tantalum Polymer, 220 uF, 10 V, +/- 20%, 0.025 ohm, AEC-Q200 Grade 1, 7343-31 SMD; Manufacturer: Kemet; PartNumber: T598D227M010ATE025; TaMin_C: -55°C; ESR_ohm: 25m; Polarized: Y; SizeAreaWB_mm2: 58.59; TaMax_C: 125°C; SizeZ_mm: 3.1; SizeX_mm: 7.3; SizeY_mm: 4.3; Cap_Case: 7.3x4.3x3.1mm; SizeArea_mm2: 31.39; CompType: Capacitor; Cap_F: 220µF; IRMS_A: 3A; AEC Grade: 1; AEC Category: Q200
C38-C41 C43-C46 C80-C83 C85-C88 = Capacitor: CAP, CERM, 100uF, 6.3V, X7S, 20%, 1210; Manufacturer: Murata; Polarized: N; U/M: EA
C42 = CMP-0006861-4: CAP, CERM, 0.1 uF, 50 V, +/- 10%, X7R, 0603; Manufacturer: Kemet; TaMin_C: -55°C; Polarized: N; SizeAreaWB_mm2: 4.68; Value1: Unknown; U/M: EA; Value: 0.1uF; TaMax_C: 125°C; SizeZ_mm: 1; SizeX_mm: 1.6; SizeY_mm: 0.8; Cap_Case: 0603; SizeArea_mm2: 1.28; AEC Category: Q200
C47 = CMP-0006861-4: CAP, CERM, 0.1 uF, 50 V, +/- 10%, X7R, 0603; PartNumber: C0603C104K5RACTU; Manufacturer: Kemet; Polarized: N; Value: 0.1uF; U/M: EA; Cap_F: 100nF; Value1: Unknown; TaMin_C: -55°C; TaMax_C: 125°C; Cap_Case: 0603; AEC Category: Q200; SizeArea_mm2: 1.28; SizeAreaWB_mm2: 4.68; SizeX_mm: 1.6; SizeY_mm: 0.8; SizeZ_mm: 1
C49 C91 = CMP-0006306-2: CAP, CERM, 0.033 uF, 25 V, +/- 10%, X7R, AEC-Q200 Grade 1, 0402; Manufacturer: TDK; Polarized: N; U/M: EA; Cap_F: 33nF; Value1: Unknown; TaMin_C: -55°C; TaMax_C: 125°C; Cap_Case: 0402; AEC Category: Q200; AEC Grade: 1; AEC Qualified: Y; SizeArea_mm2: 0.5; SizeAreaWB_mm2: 3; SizeZ_mm: 0.6
C51 C93 = CMP-0006311-2: CAP, CERM, 22 pF, 50 V, +/- 5%, C0G/NP0, AEC-Q200 Grade 1, 0402; Manufacturer: TDK; Polarized: N; Value: 22pF; U/M: EA; Value1: Unknown; TaMin_C: -55°C; TaMax_C: 125°C; Cap_Case: 0402; AEC Category: Q200; AEC Grade: 1; AEC Qualified: Y; SizeArea_mm2: 0.5; SizeAreaWB_mm2: 3; SizeZ_mm: 0.6
C52 = CMP-0006353-2: CAP, CERM, 0.022 uF, 25 V, +/- 10%, X7R, AEC-Q200 Grade 1, 0402; Manufacturer: MuRata; Polarized: N; U/M: EA; Cap_F: 22nF; Value1: Unknown; TaMin_C: -55°C; TaMax_C: 125°C; Cap_Case: 0402; AEC Category: Q200; AEC Grade: 1; AEC Qualified: Y; SizeArea_mm2: 0.5; SizeAreaWB_mm2: 3; SizeZ_mm: 0.6
C53 C95 = CMP-0006705-2: CAP, CERM, 270 pF, 100 V, +/- 10%, X7R, 0402; Manufacturer: MuRata; Polarized: N; Value: 270pF; U/M: EA; Value1: Unknown; TaMin_C: -55°C; TaMax_C: 125°C; Cap_Case: 0402; AEC Category: Q200; SizeArea_mm2: 0.5; SizeAreaWB_mm2: 3; SizeX_mm: 1; SizeZ_mm: 0.6
C54 C100 = CMP-0093675-1: 4.7uF ±10% 100V Ceramic Capacitor X7S 1210 (3225 Metric); Manufacturer: Murata; AEC Qualified: Yes; TempCo: 22%; SizeZ_mm: 2.3mm; Cap_F: 4.7µF; Value: 4.7µF; AEC Grade: Grade 1
C75 = CMP-0079150-1: CAP, CERM, 0.1 µF, 10 V,+/- 10%, X7R, AEC-Q200 Grade 1, 0402; Manufacturer: Kemet; Polarized: N; Value: 0.1uF; U/M: EA; Cap_F: 100nF; TaMin_C: -55°C; TaMax_C: 125°C; Cap_Case: 0402; AEC Category: Q200; AEC Grade: 1; AEC Qualified: Y; SizeArea_mm2: 0.5; SizeAreaWB_mm2: 3; SizeZ_mm: 0.6
C84 = CMP-0006861-4: CAP, CERM, 0.1 uF, 50 V, +/- 10%, X7R, 0603; Manufacturer: Kemet; TaMin_C: -55°C; Polarized: N; SizeAreaWB_mm2: 4.68; Value1: Unknown; U/M: EA; TaMax_C: 125°C; SizeZ_mm: 1; SizeX_mm: 1.6; SizeY_mm: 0.8; Cap_Case: 0603; SizeArea_mm2: 1.28; AEC Category: Q200
C89 = CMP-0006861-4: CAP, CERM, 0.1 uF, 50 V, +/- 10%, X7R, 0603; Manufacturer: Kemet; TaMin_C: -55°C; Polarized: N; SizeAreaWB_mm2: 4.68; Value1: Unknown; U/M: EA; TaMax_C: 125°C; SizeZ_mm: 1; SizeX_mm: 1.6; SizeY_mm: 0.8; Cap_Case: 0603; SizeArea_mm2: 1.28; Cap_F: 100nF; AEC Category: Q200
C94 = CMP-0006670-2: CAP, CERM, 5600 pF, 25 V, +/- 10%, X7R, 0402; PartNumber: GRM155R71E562KA01D; Manufacturer: MuRata; Polarized: N; Value: 5600pF; U/M: EA; Cap_F: 5.6nF; Value1: Unknown; TaMin_C: -55°C; TaMax_C: 125°C; Cap_Case: 0402; AEC Category: Q200; SizeArea_mm2: 0.5; SizeAreaWB_mm2: 3; SizeX_mm: 1; SizeZ_mm: 0.6
C102 = CMP-0093675-1: 4.7uF ±10% 100V Ceramic Capacitor X7S 1210 (3225 Metric); Manufacturer: Murata; PartNumber: GCJ32DC72A475KE01L; AEC Qualified: Yes; TempCo: 22%; SizeZ_mm: 2.3mm; Cap_F: 4.7µF; Value: 4.7µF; AEC Grade: Grade 1
D1 D5 = CMP-0076946-1: Diode, Schottky, 100 V, 0.25 A, SOD-323F; Manufacturer: Nexperia; TJmax_C: 150°C; SizeAreaWB_mm2: 7.875; SizeZ_mm: 0.8; SizeArea_mm2: 3.125; SizeY_mm: 1.25; Vf_V: 850mV; Value2: 0.85V; SizeX_mm: 2.5; Green_REACh: Incomplete; AEC Category: Q101; Value1: 0.25A; Green_Lifecycle: Not Set; Io_A: 250mA; U/M: EA
D2 D6 = CMP-0080010-1: Diode, Schottky, 100 V, 5 A, AEC-Q101, PowerDI5; Manufacturer: Diodes Inc.; SizeAreaWB_mm2: 49.56; SizeArea_mm2: 24.96; AEC Qualified: Y; TJmax_C: 175°C; AEC Category: Q101; SizeZ_mm: 1.05; Io_A: 5A; Vf_V: 710mV; SizeY_mm: 3.9; Value2: 0.71V; SizeX_mm: 6.4; RJC_CperW: 5
D3 D7 = CMP-0048085-1: Diode 40 V 10A Surface Mount TO-277A (SMPC); Manufacturer: Vishay; AEC Qualified: Yes; SizeZ_mm: 1.2mm; TJmax_C: 150°C; AEC Grade: Grade 0; Cap_F: 750pF; Max Surge Forward Current: 280A; Peak Reverse Current: 100uA
D4 D8 = Diode_Schottky: Diode, Schottky, 100V, 2A, SOD-123; Manufacturer: Nexperia; PartNumber: PMEG10020AELRX; U/M: EA
J1 J2 J7 J9-J11 = CMP-0055135-1: Shorting Jumper, 5.375mm, 2 Position, Tin, SMT; Manufacturer: Keystone; CNHeader: FALSE; Pitch_mm: 5.375
J3 J4 = CMP-0079575-1: Banana Jack Insul Nylon Red, TH; PartNumber: 108-0902-001; Manufacturer: Cinch Connectivity; Gender: Female; Current_A: 15A; Green_REACh: Incomplete; ContactFinish: Tin; Green_Lifecycle: Active
J5 J6 = CMP-0079574-1: Banana Jack Insul Nylon Black, TH; PartNumber: 108-0903-001; Manufacturer: Cinch Connectivity; Gender: Female; Current_A: 15A; Green_REACh: Incomplete; ContactFinish: Tin; Green_Lifecycle: Active
J8 J12 = CMP-0075405-3: Header, 100mil, 2x1, Gold, TH; Manufacturer: Samtec; Current_A: 6.3A; Green_Lifecycle: Active; Pitch_mm: 2.54; Cert_CSA: Y; Cert_VDE: N; Green_REACh: Passed; Row_Count: 1; Gender: Male; Voltage_V: 550V
L1 = CMP-0048360-1: 1 µH Shielded Molded Inductor 22 A 2.9mOhm Max Nonstandard; Manufacturer: Coilcraft; Self Resonant Frequency: 46MHz; AEC Grade: Grade 1; Isat: 11A; Tolerance_%: 20%; DCR_ohm: 2.9m; Ind_H: 1µH; Irms: 22A; Material: Composite; SizeZ_mm: 6.1mm; Test Frequency: 1MHz; Shrouded: true; TaMin_C: -40°C; TaMax_C: +125°C; AEC Qualified: Yes
L2 = CMP-0084691-1: Coupled inductor,  ohm, AEC-Q200 Grade 1, SMD; Manufacturer: TDK; AEC Grade: 1; AEC Category: Q200; SizeZ_mm: 6; SizeX_mm: 12; AEC Qualified: Y; SizeAreaWB_mm2: 182; SizeArea_mm2: 132; SizeY_mm: 11
L3 = CMP-0013197-2: Coupled inductor, 2 uH,  A, 1.8 ohm, SMD; Manufacturer: MuRata; SizeAreaWB_mm2: 128.14; DCR_ohm: 1.8; Value: 2uH; SizeZ_mm: 9.4; SizeX_mm: 6.6; SizeY_mm: 12.9; SizeArea_mm2: 85.14; Ind_H: 2µH
L4 L6 = Inductor: Inductor, Composite, 2.2uH, 1.5mOhm Max., 15.2mm x 13.6mm x 13.0mm, SMT; Manufacturer: Coilcraft; U/M: EA
L5 L7 = CMP-0047844-1: Power Choke Coil 2.5uH 20% 100kHz 2.53mOhm 32A AECQ200 13.3x12.8x8.0mm SMT; Manufacturer: CYNTEC; Isat: 30A; DCR_ohm: 2.53m; Material: Metal Dust; SizeZ_mm: 8mm; Ind_H: 2.5µH; AEC Qualified: Yes; AEC Grade: Grade 0
NT1-NT5 = CMP-0078142-3: Single point connection between nets.
Q1 Q2 Q7 Q8 = CMP-0094035-1: MOSFET N-Channel 80 V 13A (Ta), 59A (Tc) 3.7W (Ta), 73W (Tc) Surface Mount 5-DFN (5x6) (8-SOFL); Manufacturer: onsemi; Vgs_V: 20V; Input Capacitace At Vds: 1420pF @ 40V; SizeZ_mm: 1.1mm; Transconductance: 84S; Pulse Drain Current: 319A; Turn Off Delay Time: 22ns; Rdson45_ohm: 8.8m; AEC Grade: Grade 0; Reverse Recovery Time: 39ns; Threshold Vgs Max: 2V; VdsMax_V: 1.2V; Number Of N Channels: 1; Turn On Delay Time: 37ns; QgTyp_nC: 25nC @ 10V; Standoff Height: 0mm; Rthja Max: 41°C/W; Reverse Recovery Charge: 36nC; AEC Qualified: Yes; TJmax_C: +175°C; ChMode: False; Typ Forward Diode Voltage: 0.81V
Q4 Q5 Q9 Q10 = CMP-0032024-1: N-Channel 80 V 24A (Ta), 160A (Tc) 3.8W (Ta), 167W (Tc) Surface Mount 5-DFN (5x6) (8-SOFL); Manufacturer: onsemi; AEC Qualified: Yes; QgTyp_nC: 90nC @ 10V; Rdson45_ohm: 2.6m; SizeZ_mm: 1.1mm; VdsMax_V: 1.2V; Vgs_V: 20V; ChMode: False; AEC Grade: Grade 0; Input Capacitace At Vds: 5126pF @ 40V; Number Of Channels: 1; Pulse Drain Current: 900A; Reverse Recovery Charge: 92nC; Reverse Recovery Time: 66ns; Rthja Max: 39°C/W; Standoff Height: 0mm; Threshold Vgs Max: 2V; TJmax_C: +175°C; Transconductance: 240S; Turn Off Delay Time: 50ns; Turn On Delay Time: 25ns; Typ Forward Diode Voltage: 0.76V
R1 R2 = CMP-0015904-3: RES, 1.0, 5%, 1 W, AEC-Q200 Grade 0, 2512; Manufacturer: Vishay-Dale; Power_W: 1W; TempCo: 200 ppm/C; Value_Code: 1R00; Value: 1.0; EIA_Code: E24; Res_ohm: 1; SizeX_mm: 6.3; SizeY_mm: 3.2; SizeZ_mm: 0.71; SizeArea_mm2: 20.16; AEC Qualified: Y; VDC_V: 500V; AEC Grade: 0; AEC Category: Q200
R3 R4 R54 R56 = CMP-0023343-3: RES, 0, 1%, 0.1 W, AEC-Q200 Grade 0, 0603; Manufacturer: Stackpole Electronics Inc; Power_W: 100mW; TempCo: ppm/C; Value: 0; SizeX_mm: 1.6; SizeY_mm: 0.8; SizeZ_mm: 1; Value2: 0.1W; SizeArea_mm2: 1.28; AEC Qualified: Y; AEC Category: Q200; U/M: EA
R5 R30 R66 R67 = CMP-0046355-1: Res Current Sense Thick Film 1225 0.5m Ohm 5% 2W ±150ppm/°C Molded Emboss T/R; Manufacturer: Rohm Semiconductor; PartNumber: PML100HZPJV0L5; AEC Grade: Grade 0; AEC Qualified: Yes; SizeZ_mm: 0.65mm
R6 = CMP-0022060-4: RES, 150 k, 1%, 0.1 W, AEC-Q200 Grade 0, 0603; Manufacturer: Vishay-Dale; Power_W: 100mW; TempCo: 100 ppm/C; Value: 150k; EIA_Code: E96; SizeX_mm: 1.6; SizeY_mm: 0.8; SizeZ_mm: 1; Value2: 0.1W; SizeArea_mm2: 1.28; AEC Qualified: Y; VDC_V: 75V; AEC Category: Q200; AEC Grade: 0
R7 = CMP-0081856-1: RES, 0, 0%, 0.2 W, AEC-Q200 Grade 0, 0402; Manufacturer: Vishay-Dale; Value: 0; Power_W: 200mW; Value2: 0.2W; VDC_V: 50V; AEC Category: Q200; AEC Qualified: Y; SizeArea_mm2: 0.5; SizeX_mm: 1; SizeZ_mm: 0.6; SizeAreaWB_mm2: 3
R8 R33 = CMP-0001672-1: 1.2 mOhms ±1% 5W Chip Resistor 2512 (6432 Metric) Automotive AEC-Q200, Current Sense, Non-Inductive Metal Element; Manufacturer: Vishay Foil Resistors; Value: 1.2m; AEC Qualified: Yes; AEC Grade: Grade 0
R9 = CMP-0026517-2: RES, 6.81 k, 1%, 0.063 W, AEC-Q200 Grade 0, 0402; Manufacturer: Vishay-Dale; Power_W: 63mW; TempCo: 100 ppm/C; Value_Code: 6k81; Value: 6.81k; EIA_Code: E96; SizeX_mm: 1; SizeY_mm: 0.5; SizeZ_mm: 0.6; Value2: 0.063W; AEC Qualified: Y; VDC_V: 50V; AEC Category: Q200; AEC Grade: 0
R10 R19 R46 = CMP-0026753-1: RES, 100 k, 1%, 0.063 W, AEC-Q200 Grade 0, 0402; PartNumber: RMCF0402FT100K; Manufacturer: Stackpole Electronics Inc; Value: 100k; Power_W: 63mW; Value2: 0.063W; VDC_V: 50V; TempCo: 100 ppm/C; EIA_Code: E96; AEC Category: Q200; AEC Grade: 0; AEC Qualified: Y; SizeArea_mm2: 0.5; SizeX_mm: 1; SizeZ_mm: 0.6; U/M: EA
R11 R16 R36 R41 = Resistor: RES, xxx ohm, x%, xW, [PackageReference]; Manufacturer: Used in BOM report; U/M: EA
R12 R37 = CMP-0026404-2: RES, 49.9, 1%, 0.063 W, AEC-Q200 Grade 0, 0402; Manufacturer: Vishay-Dale; Value: 49.9; Value_Code: 49R9; Power_W: 63mW; Value2: 0.063W; VDC_V: 50V; TempCo: 100 ppm/C; EIA_Code: E96; AEC Category: Q200; AEC Grade: 0; AEC Qualified: Y; SizeArea_mm2: 0.5; SizeX_mm: 1; SizeZ_mm: 0.6
R13 R38 R53 = CMP-0086542-2: RMCF/RMCP Series General Purpose Thick Film Standard Power and High Power Chip Resistor; Manufacturer: Stackpole
R14 R39 = Resistor: RES, 1.0 ohm, 5%, 0.5W, 1210; Manufacturer: Stackpole; PartNumber: RMCF1210JT4R70; U/M: EA
R15 R20 R40 R45 = CMP-0081856-1: RES, 0, 0%, 0.2 W, AEC-Q200 Grade 0, 0402; PartNumber: CRCW04020000Z0EDHP; Manufacturer: Vishay-Dale; SizeAreaWB_mm2: 3; SizeArea_mm2: 0.5; AEC Qualified: Y; AEC Category: Q200; Value: 0; SizeZ_mm: 0.6; Power_W: 200mW; VDC_V: 50V; Value2: 0.2W; SizeX_mm: 1
R17 = CMP-0022448-4: RES, 49.9, 1%, 0.1 W, AEC-Q200 Grade 0, 0603; Manufacturer: Vishay-Dale; Value: 49.9; Value_Code: 49R9; Power_W: 100mW; Value2: 0.1W; VDC_V: 75V; TempCo: 100 ppm/C; EIA_Code: E96; AEC Category: Q200; AEC Grade: 0; AEC Qualified: Y; SizeArea_mm2: 1.28; SizeX_mm: 1.6; SizeY_mm: 0.8; SizeZ_mm: 1
R18 R44 = CMP-0026013-3: RES, 147 k, 1%, 0.063 W, AEC-Q200 Grade 0, 0402; Manufacturer: Vishay-Dale; Value: 147k; Power_W: 63mW; Value2: 0.063W; VDC_V: 50V; TempCo: 100 ppm/C; EIA_Code: E96; AEC Category: Q200; AEC Grade: 0; AEC Qualified: Y; SizeArea_mm2: 0.5; SizeX_mm: 1; SizeZ_mm: 0.6
R22 = CMP-0026399-2: RES, 48.7 k, 1%, 0.063 W, AEC-Q200 Grade 0, 0402; Manufacturer: Vishay-Dale; PartNumber: CRCW040248K7FKED; Power_W: 63mW; TempCo: 100 ppm/C; Value_Code: 48k7; Value: 48.7k; EIA_Code: E96; SizeX_mm: 1; SizeY_mm: 0.5; SizeZ_mm: 0.6; Value2: 0.063W; AEC Qualified: Y; VDC_V: 50V; AEC Category: Q200; AEC Grade: 0
R23 = CMP-0026753-1: RES, 100 k, 1%, 0.063 W, AEC-Q200 Grade 0, 0402; Manufacturer: Stackpole Electronics Inc; Power_W: 63mW; TempCo: 100 ppm/C; Value: 100k; EIA_Code: E96; SizeX_mm: 1; SizeY_mm: 0.5; SizeZ_mm: 0.6; Value2: 0.063W; AEC Qualified: Y; VDC_V: 50V; AEC Category: Q200; AEC Grade: 0; U/M: EA
R24 = CMP-0026329-2: RES, 3.01 k, 1%, 0.063 W, AEC-Q200 Grade 0, 0402; Manufacturer: Vishay-Dale; Value: 3.01k; Value_Code: 3k01; Power_W: 63mW; Value2: 0.063W; VDC_V: 50V; TempCo: 100 ppm/C; EIA_Code: E96; AEC Category: Q200; AEC Grade: 0; AEC Qualified: Y; SizeArea_mm2: 0.5; SizeX_mm: 1; SizeZ_mm: 0.6
R25 = CMP-0026449-2: RES, 54.9 k, 1%, 0.063 W, AEC-Q200 Grade 0, 0402; Manufacturer: Vishay-Dale; Value: 54.9k; Value_Code: 54k9; Power_W: 63mW; Value2: 0.063W; VDC_V: 50V; TempCo: 100 ppm/C; EIA_Code: E96; AEC Category: Q200; AEC Grade: 0; AEC Qualified: Y; SizeArea_mm2: 0.5; SizeX_mm: 1; SizeZ_mm: 0.6
R26 = CMP-0026067-3: RES, 19.1 k, 1%, 0.063 W, AEC-Q200 Grade 0, 0402; Manufacturer: Vishay-Dale; Power_W: 63mW; TempCo: 100 ppm/C; Value_Code: 19k1; Value: 19.1k; EIA_Code: E96; SizeX_mm: 1; SizeY_mm: 0.5; SizeZ_mm: 0.6; Value2: 0.063W; AEC Qualified: Y; VDC_V: 50V; AEC Category: Q200; AEC Grade: 0
R29 = CMP-0021990-4: RES, 100 k, 1%, 0.1 W, AEC-Q200 Grade 0, 0603; Manufacturer: Vishay-Dale; PartNumber: CRCW0603100KFKEA; Power_W: 100mW; TempCo: 100 ppm/C; Value: 100k; EIA_Code: E96; SizeX_mm: 1.6; SizeY_mm: 0.8; SizeZ_mm: 1; Value2: 0.1W; SizeArea_mm2: 1.28; AEC Qualified: Y; VDC_V: 75V; AEC Category: Q200; AEC Grade: 0
R31 R32 R43 R49 = CMP-0081856-1: RES, 0, 0%, 0.2 W, AEC-Q200 Grade 0, 0402; Manufacturer: Vishay-Dale; SizeAreaWB_mm2: 3; SizeArea_mm2: 0.5; AEC Qualified: Y; AEC Category: Q200; Value: 0; SizeZ_mm: 0.6; Power_W: 200mW; VDC_V: 50V; Value2: 0.2W; SizeX_mm: 1
R34 = CMP-0026412-2: RES, 4.75 k, 1%, 0.063 W, AEC-Q200 Grade 0, 0402; Manufacturer: Vishay-Dale; PartNumber: CRCW04024K75FKED; Power_W: 63mW; TempCo: 100 ppm/C; Value_Code: 4k75; Value: 4.75k; EIA_Code: E96; SizeX_mm: 1; SizeY_mm: 0.5; SizeZ_mm: 0.6; Value2: 0.063W; AEC Qualified: Y; VDC_V: 50V; AEC Category: Q200; AEC Grade: 0
R35 = CMP-0026753-1: RES, 100 k, 1%, 0.063 W, AEC-Q200 Grade 0, 0402; Manufacturer: Stackpole Electronics Inc; Value: 100k; Power_W: 63mW; Value2: 0.063W; VDC_V: 50V; TempCo: 100 ppm/C; EIA_Code: E96; AEC Category: Q200; AEC Grade: 0; AEC Qualified: Y; SizeArea_mm2: 0.5; SizeX_mm: 1; SizeZ_mm: 0.6; U/M: EA
R42 = CMP-0022448-4: RES, 49.9, 1%, 0.1 W, AEC-Q200 Grade 0, 0603; PartNumber: CRCW060349R9FKEA; Manufacturer: Vishay-Dale; Value: 49.9; Value_Code: 49R9; Power_W: 100mW; Value2: 0.1W; VDC_V: 75V; TempCo: 100 ppm/C; EIA_Code: E96; AEC Category: Q200; AEC Grade: 0; AEC Qualified: Y; SizeArea_mm2: 1.28; SizeX_mm: 1.6; SizeY_mm: 0.8; SizeZ_mm: 1
R48 = CMP-0026555-2: RES, 7.50 k, 1%, 0.063 W, AEC-Q200 Grade 0, 0402; PartNumber: CRCW04027K50FKED; Manufacturer: Vishay-Dale; Value: 7.50k; Res_ohm: 7.5k; Value_Code: 7k50; Power_W: 63mW; Value2: 0.063W; VDC_V: 50V; TempCo: 100 ppm/C; EIA_Code: E96; AEC Category: Q200; AEC Grade: 0; AEC Qualified: Y; SizeArea_mm2: 0.5; SizeX_mm: 1; SizeZ_mm: 0.6
R50 = CMP-0026753-1: RES, 100 k, 1%, 0.063 W, AEC-Q200 Grade 0, 0402; Manufacturer: Stackpole Electronics Inc; PartNumber: RMCF0402FT100K; Power_W: 63mW; TempCo: 100 ppm/C; Value: 100k; EIA_Code: E96; SizeX_mm: 1; SizeY_mm: 0.5; SizeZ_mm: 0.6; Value2: 0.063W; AEC Qualified: Y; VDC_V: 50V; AEC Category: Q200; AEC Grade: 0; U/M: EA
R51 = CMP-0086542-2: RMCF/RMCP Series General Purpose Thick Film Standard Power and High Power Chip Resistor; Manufacturer: Stackpole; PartNumber: RMCF0402ZT0R00
R52 = CMP-0026605-2: RES, 90.9 k, 1%, 0.063 W, AEC-Q200 Grade 0, 0402; Manufacturer: Vishay-Dale; Value: 90.9k; Value_Code: 90k9; Power_W: 63mW; Value2: 0.063W; VDC_V: 50V; TempCo: 100 ppm/C; EIA_Code: E96; AEC Category: Q200; AEC Grade: 0; AEC Qualified: Y; SizeArea_mm2: 0.5; SizeX_mm: 1; SizeZ_mm: 0.6
R64 R65 = CMP-0001672-1: 1.2 mOhms ±1% 5W Chip Resistor 2512 (6432 Metric) Automotive AEC-Q200, Current Sense, Non-Inductive Metal Element; Manufacturer: Vishay Foil Resistors; PartNumber: Y14830R00120F9R; Value: 1.2m; AEC Qualified: Yes; AEC Grade: Grade 0
SH-J1 SH-J2 = CMP-0003761-2: Shunt, 2.54mm, Gold, Black; Manufacturer: Wurth Elektronik
T1-T3 = CMP-0055443-2: Terminal 90A Lug; Manufacturer: Panduit; Green_Lifecycle: Not Set; Cert_CULUS: Y; Green_REACh: Incomplete; Voltage_V: 600V; CompType: Screw Terminal; ContactFinish: Copper
TP1 TP2 = CMP-0055153-2: Test Point, Compact, SMT; Manufacturer: Keystone Electronics; Green_Lifecycle: Active; Green_REACh: Passed; CNHeader: FALSE; CT: TRUE
TP3 TP9 = CMP-0055147-1: Test Point, Multipurpose, Red, TH; Manufacturer: Keystone; CNHeader: FALSE; Green_Lifecycle: Active; Green_REACh: Passed; ContactFinish: Silver; CT: TRUE
TP4-TP6 TP10-TP12 = CMP-0055149-1: Test Point, Multipurpose, White, TH; Manufacturer: Keystone; CNHeader: FALSE; Green_Lifecycle: Active; Green_REACh: Passed; ContactFinish: Silver; CT: TRUE
TP7 TP8 = CMP-0055148-1: Test Point, Multipurpose, Black, TH; Manufacturer: Keystone; CNHeader: FALSE; Green_Lifecycle: Active; Green_REACh: Passed; ContactFinish: Silver; CT: TRUE
U2 U5 = CMP-0032794-1: 80-V, Automotive, Synchronous, Buck DC/DC Controller with Ultra-Low IQ and Dual Random Spread Spectrum; Manufacturer: Texas Instruments; SizeZ_mm: 1mm; AEC Qualified: Yes; AEC Grade: Grade 1; Max Duty Cycle: 100%; Max Supply Voltage: 80V; Min Supply Voltage: 3.5V; Nominal Supply Current: 9.5-124uA; Number Of Outputs: 1; Output Type: Fixed,AdjustableProgrammable; Output Voltage: 3/5/12/0.8-55V; Standoff Height: 0mm; Switching Frequency: 100-2200kHz; TaMax_C: +125°C; TaMin_C: -40°C; TJmax_C: +150°C

## Sheet PMP23420_Hardware.SchDoc
size 431 x 279 mm; Date: Not shown in title block; ApprovedBy: Not shown in title block; CheckedBy: Not shown in title block; Author: Not shown in title block; CompanyName: Not shown in title block; Engineer: Not shown in title block; Organization: Not shown in title block; Address1: Not shown in title block; Address2: Not shown in title block; Address3: Not shown in title block; Address4: Not shown in title block; DocumentNumber: 2; Revision: Use project parameter SCH_Rev; SheetNumber: 2; SheetTotal: 2; PageSetup: Record=PageOptions¦CenterHorizontal=True¦CenterVertical=True¦PrintScale=1.00¦XCorrection=1.00¦YCorrection=1.00¦PrintKind=0¦BorderSize=5000000¦LeftOffset=0¦BottomOffset=0¦Orientation=2¦PaperLength=1000¦PaperWidth=1000¦Scale=100¦PaperSource=15¦PrintQuality=600¦MediaType=1¦DitherType=10¦PaperKind=Letter¦PrintScaleMode=1
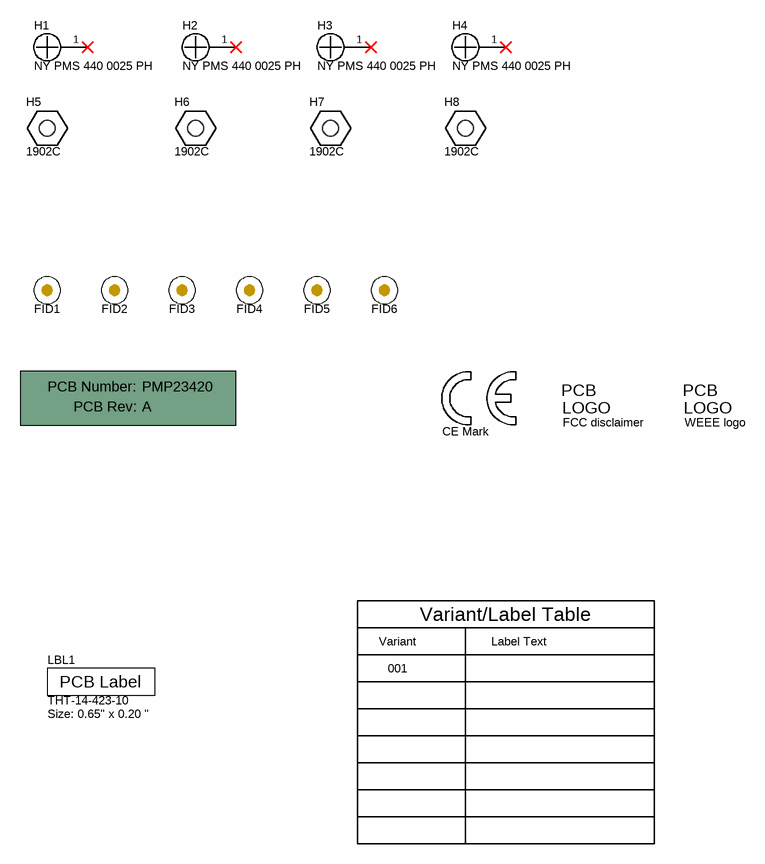
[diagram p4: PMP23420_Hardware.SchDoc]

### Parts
!PCB1  Printed Circuit Board  (value not drawn)  (mechanical)
FID1  Fiducial  [Fiducial10-20]  (value not drawn)
FID2  Fiducial  [Fiducial10-20]  (value not drawn)
FID3  Fiducial  [Fiducial10-20]  (value not drawn)
FID4  Fiducial  [Fiducial10-20]  (value not drawn)
FID5  Fiducial  [Fiducial10-20]  (value not drawn)
FID6  Fiducial  [Fiducial10-20]  (value not drawn)
H1  NY PMS 440 0025 PH  [NY PMS 440 0025 PH]
H2  NY PMS 440 0025 PH  [NY PMS 440 0025 PH]
H3  NY PMS 440 0025 PH  [NY PMS 440 0025 PH]
H4  NY PMS 440 0025 PH  [NY PMS 440 0025 PH]
H5  1902C  [Keystone_1902C]
H6  1902C  [Keystone_1902C]
H7  1902C  [Keystone_1902C]
H8  1902C  [Keystone_1902C]
LBL1  THT-14-423-10  Note: Size: 0.65" x 0.20 "  [Label_650x200]
Logo1  CE Mark  [CE_Mark_5mm]  (no BOM)
Logo2  FCC disclaimer  [FCC_disclaimer]  (no BOM)
Logo3  WEEE logo  [WEEE_Minimum]  (no BOM)

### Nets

Not connected (* = marked no-connect by the designer): H1 1*; H2 1*; H3 1*; H4 1*

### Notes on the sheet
- Variant
- Variant/Label Table
- Label Text
- 001

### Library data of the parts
!PCB1 = CMP-0003618-2: Manufacturer: Any; PartNumber: PMP23420
FID1-FID6 = CMP-0077181-1: Fiducial mark.  There is nothing to buy or mount.
H1-H4 = CMP-0003617-1: Machine Screw, Round, #4-40 x 1/4, Nylon, Philips panhead; Manufacturer: B&F Fastener Supply; CompType: Hardware
H5-H8 = CMP-0003610-1: Standoff, Hex, 0.5"L #4-40 Nylon; Manufacturer: Keystone; CompType: Hardware
LBL1 = CMP-0003625-1: Thermal Transfer Printable Labels, 0.650" W x 0.200" H - 10,000 per roll; Manufacturer: Brady; CompType: Label
Logo1 = CMP-0074844-1: SymbolCreator: a0412235
Logo2 = CMP-0074847-1: FCC_disclaimer; Library Reference: Logo
Logo3 = CMP-0074769-1

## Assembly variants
001: not fitted C21 C22 C23 C24 C25 C26 C27 C28 C29 C35 C63 C64 C65 C66 C67 C68 C69 C70 C71 C77 C94 C102 C103 D4 D8 FID1 FID2 FID3 FID4 FID5 FID6 L1 L2 L3 L5 L7 R5 R10 R11 R14 R15 R16 R19 R22 R29 R30 R34 R36 R39 R40 R41 R42 R45 R46 R48 R50 R51 R64 R65 R66 R67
